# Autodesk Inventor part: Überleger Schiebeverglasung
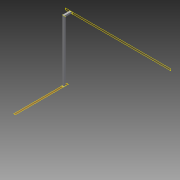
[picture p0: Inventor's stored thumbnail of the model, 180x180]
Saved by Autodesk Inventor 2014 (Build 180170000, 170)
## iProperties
Created: 2013-09
Part Number: Überleger Schiebeverglasung
Material: Stahl
Document SubType Name: Modeling
Designer: Stefan Tammegger
Mass: 21002.8 g
Surface Area: 17855.1 cm^2
Volume: 2675.52 cm^3
Density: 7.85 g/cm^3
Appearance: Stahl
Author: Stefan Tammegger
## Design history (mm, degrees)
node "Blöcke"
  sketch "FR 80_80_3"
    geometry: L1 (-331.019, -2889.589)-(-257.019, -2889.589); L2 (-254.019, -2892.589)-(-254.019, -2966.589); L3 (-257.019, -2969.589)-(-331.019, -2969.589); L4 (-334.019, -2966.589)-(-334.019, -2892.589); L5 (-257.019, -2892.589)-(-331.019, -2892.589); L6 (-331.019, -2892.589)-(-331.019, -2966.589); L7 (-331.019, -2966.589)-(-257.019, -2966.589); L8 (-257.019, -2966.589)-(-257.019, -2892.589); A1 r 3 centre (-331.019, -2892.589) between (-331.019, -2889.589) and (-334.019, -2892.589); A2 r 3 centre (-257.019, -2892.589) between (-254.019, -2892.589) and (-257.019, -2889.589); A3 r 3 centre (-257.019, -2966.589) between (-257.019, -2969.589) and (-254.019, -2966.589); A4 r 3 centre (-331.019, -2966.589) between (-334.019, -2966.589) and (-331.019, -2969.589); 4 further points
    constraints: 16 end point, 8 point on circle, 8 tangent, 6 point on line, 4 centre point, 4 parallel, 3 equal radius, 2 perpendicular, 1 horizontal, 1 midpoint, 3 other
    dimensions: "d0" = 80 distance of point (-254.019, -2969.589) point (-334.019, -2969.589); "d1" = 80 distance of point (-254.019, -2889.589) point (-254.019, -2969.589); "d2" = 3 distance between parallel lines of L1 L5; "d3" = 3 radius of A1
workplane "Arbeitsebene1"
sketch "Skizze1"
  geometry: L1 (117, 0)-(-253, 0) reference; L2 (-3, 10)-(-3, 2290) reference; L3 (77, 10)-(77, 2290) reference; 1 further point
  constraints: 1 vertical
  dimensions: "d4" = 2200 dimension on L1
  node "Referenz1"
  node "Referenz2"
  node "Referenz3"
  node "FR 80_80_3:1" dims "d4" = 2200
workplane "Arbeitsebene2"
extrude "Extrusion1" new body sketch "Skizze1" stored distance "d5" = 10; taper "d6" = 0 deg
workplane "Arbeitsebene3"
sketch "Skizze2"
  geometry: L1 (74, 2280)-(0, 2280) reference; L2 (-3, 2277)-(-3, 2203) reference; L3 (77, 2203)-(77, 2277) reference; L4 (0, 2200)-(74, 2200) reference; L5 (-3, 2280)-(77, 2280); L6 (77, 2280)-(77, 2160); L7 (77, 2160)-(-3, 2160); L8 (-3, 2160)-(-3, 2280); 1 further point
  constraints: 8 end point, 2 collinear, 2 parallel, 1 horizontal, 1 perpendicular
  dimensions: "d7" = 80 distance of L6.end L7.end; "d8" = 120 distance of L5.end L6.end
extrude "Extrusion2" new body sketch "Skizze2" distance "d9" = 10; taper "d10" = 0 deg
sketch "Skizze3"
  geometry: L1 (77, 2280)-(-3, 2280) reference; L2 (-3, 2280)-(-3, 2160) reference; L3 (-3, 2160)-(77, 2160) reference; L4 (77, 2160)-(77, 2280) reference; L5 (61, 2176)-(13, 2176); L6 (13, 2176)-(13, 2264); L7 (13, 2264)-(61, 2264); L8 (61, 2264)-(61, 2176); 1 further point
  constraints: 8 end point, 3 other
  dimensions: "d11" = 16 distance between parallel lines of L3 L5
hole "Bohrung1" sketch "Skizze3" at (13, 2176), (61, 2176) diameter "d12" = 12; stored, may be unused: countersink angle "d16" = 90 deg, drill point angle "d18" = 118 deg; dims "d13" = 6, "d14" = 21, "d15" = 2, "d17" = 8
workplane "Arbeitsebene4"
feature "Trennen1"
sketch "Skizze4"
  geometry: L1 (5, 100)-(4531.608, 100) reference; L2 (5, 20)-(4551.554, 20) reference; L3 (77, 2910)-(77, 0) reference; L4 (-3, 2910)-(-3, 0) reference; L5 (5, 15.783)-(5, 3333.111) reference; L6 (65, 3333.111)-(65, 15.783) reference; 1 further point
  constraints: 1 horizontal, 1 vertical
extrude "Extrusion3" new body sketch "Skizze4" stored distance "d20" = 200; taper "d21" = 0 deg
sketch "Skizze5"
  geometry: L1 (74, 97)-(74, 23) reference; L2 (74, 23)-(0, 23) reference; L3 (0, 23)-(0, 97) reference; L4 (0, 97)-(74, 97) reference; L5 (74, 100)-(0, 100) reference; L6 (-3, 97)-(-3, 23) reference; L7 (0, 20)-(74, 20) reference; L8 (77, 23)-(77, 97) reference; A1 r 3 centre (0, 97) between (0, 100) and (-3, 97) reference; A2 r 3 centre (0, 23) between (-3, 23) and (0, 20) reference; A3 r 3 centre (74, 23) between (74, 20) and (77, 23) reference; A4 r 3 centre (74, 97) between (77, 97) and (74, 100) reference; 1 further point
workplane "Arbeitsebene5"
extrude "Extrusion4" join sketch "Skizze5" stored distance "d22" = 200; taper "d23" = 0 deg
workplane "Arbeitsebene6"
feature "Trennen2"
feature "Trennen3"
workplane "Arbeitsebene7"
sketch "Skizze6"
  geometry: L1 (-410, 2886)-(-410, -1) reference; L2 (-413, -4)-(-487, -4) reference; L3 (-490, 2886)-(-490, -1) reference; L4 (-418, -4)-(-4964.554, -4) reference; L5 (-418, 76)-(-4944.608, 76) reference; L6 (-410, -4)-(-530, -4); L7 (-530, -4)-(-530, 76); L8 (-530, 76)-(-410, 76); L9 (-410, 76)-(-410, -4); 1 further point
  constraints: 8 end point, 2 collinear, 2 parallel, 1 horizontal, 1 perpendicular
  dimensions: "d24" = 120 distance of L7.end L8.end; "d25" = 80 distance of L6.end L7.end
extrude "Extrusion5" new body sketch "Skizze6" distance "d26" = 8; taper "d27" = 0 deg
workplane "Arbeitsebene8"
feature "Trennen4"
sketch "Skizze7"
  geometry: L1 (530, 4)-(410, 4) reference; L2 (410, -76)-(530, -76) reference; L3 (530, -76)-(530, 4) reference; 3 further points
  dimensions: "d29" = 15 distance from line of point (510, -11) L1; "d30" = 15 distance from line of L2 point (510, -61); "d31" = 20 distance from line of L3 point (510, -61); "d32" = 20 distance from line of L3 point (510, -11)
hole "Bohrung2" sketch "Skizze7" at (510, -11), (510, -61) diameter "d33" = 14; stored, may be unused: countersink angle "d37" = 90 deg, drill point angle "d39" = 118 deg; dims "d34" = 6, "d35" = 4, "d36" = 2, "d38" = 8
sketch "Skizze8"
  geometry: C1 r 4 at (39, -210) reference; C2 r 4 at (39, -1400) reference; C3 r 4 at (39, -2590) reference; 1 further point
hole "Bohrung3" sketch "Skizze8" at (39, -210), (39, -1400), (39, -2590) diameter "d40" = 6.647; stored, may be unused: countersink angle "d44" = 90 deg, drill point angle "d46" = 118 deg; dims "d41" = 6, "d42" = 4, "d43" = 2, "d45" = 8
node "Volumenkörper1"
node "Volumenkörper2"
node "Referenz4"
node "Referenz5"
node "Referenz6"
node "Referenz7"
node "Volumenkörper3"
node "Referenz8"
node "Referenz9"
node "Volumenkörper4"
node "Referenz10"
node "Referenz11"
node "Referenz12"
node "FR 80_80_3:2"
other parameters: "d19" = 0, "d28" = 0
